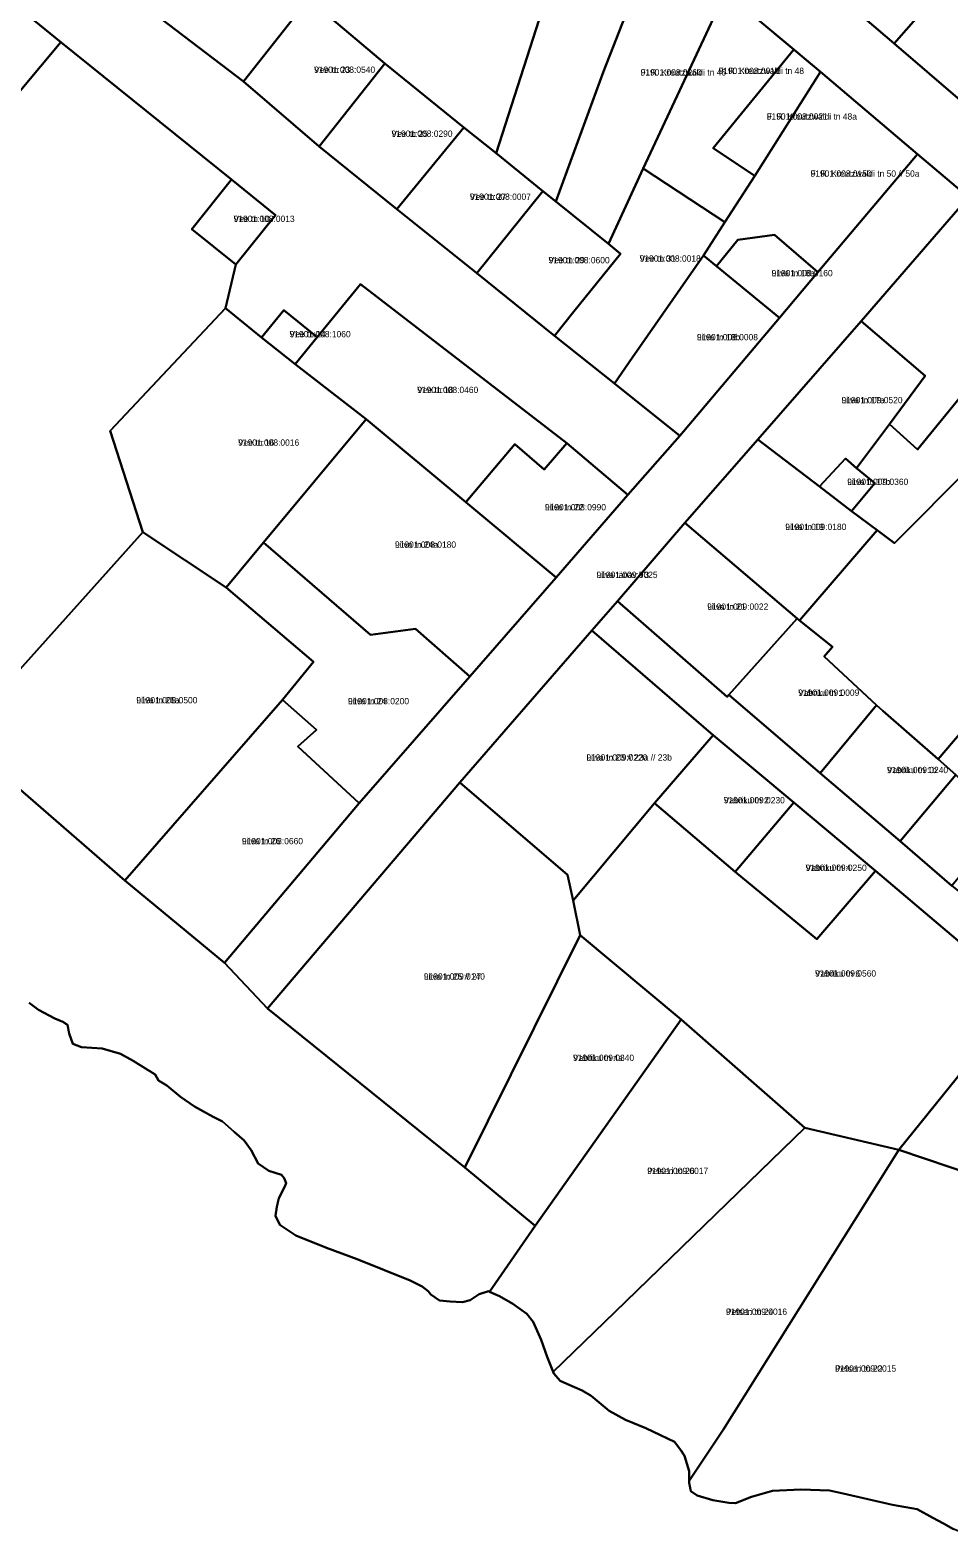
# Model space of a CAD drawing. Extents: x 675810 to 681273, y 6411190 to 6417565.
# Drawn here: x 677826.5 to 678044.7, y 6414897.9 to 6415256.1 of the extents above; entities that cross this region are included whole.
import ezdxf

# ---------------------------------------------------------------- set-up
doc = ezdxf.new("R2010")
doc.units = 0
for name, color, linetype in [('L_AADRESS', 7, 'Continuous'), ('PIIR', 7, 'Continuous'), ('TUNNUS', 7, 'Continuous')]:
    doc.layers.add(name, color=color, linetype=linetype)

msp = doc.modelspace()

# ---------------------------------------------------------------- linework, layer by layer
at = {"layer": 'PIIR'}
for points in [[(678012.96, 6415269), (678038.09, 6415299.36), (678046.57, 6415309.87), (678058.57, 6415324.78), (678069.24, 6415315.72), (678073.05, 6415320.22), (678083.66, 6415311.71), (678061.03, 6415286.5), (678046.56, 6415269.92), (678031.73, 6415252.94)], [(677892.64, 6415263.56), (677934.03, 6415314.81), (677961.35, 6415291.71), (677955.15, 6415284.36), (677947.4, 6415258.61), (677937.16, 6415226.86), (677929.54, 6415233.01), (677910.72, 6415248.23)], [(677975.47, 6415278.9), (677962.72, 6415246.32), (677951.38, 6415215.39), (677948.28, 6415217.88), (677937.16, 6415226.86), (677947.4, 6415258.61), (677955.15, 6415284.36), (677961.35, 6415291.71)], [(677793.94, 6415285.62), (677833.78, 6415253.28), (677776.13, 6415184.33), (677736.95, 6415218.9)], [(677892.64, 6415263.56), (677877.18, 6415243.9), (677857.64, 6415258.81), (677874.22, 6415278.56)], [(677991.64, 6415265.17), (677972.12, 6415223.24), (677963.91, 6415205.32), (677951.38, 6415215.39), (677962.72, 6415246.32), (677975.47, 6415278.9)], [(678046.56, 6415269.92), (678062.66, 6415256.13), (678047.94, 6415239.03), (678031.73, 6415252.94)], [(677910.72, 6415248.23), (677895.15, 6415228.47), (677877.18, 6415243.9), (677892.64, 6415263.56)], [(677991.64, 6415265.17), (678007.94, 6415251.52), (677988.71, 6415228.09), (677998.61, 6415221.54), (677991.52, 6415210.48), (677972.12, 6415223.24)], [(677809.68, 6415088.2), (677743.82, 6415145.67), (677750.89, 6415154.12), (677771.65, 6415178.95), (677776.13, 6415184.33), (677833.78, 6415253.28), (677874.3, 6415220.63), (677864.87, 6415208.84), (677875.38, 6415200.45), (677872.93, 6415190.08), (677845.5, 6415160.96), (677853.28, 6415136.87)], [(678007.94, 6415251.52), (678014.26, 6415246.19), (677998.61, 6415221.54), (677988.71, 6415228.09)], [(677913.61, 6415213.61), (677895.15, 6415228.47), (677910.72, 6415248.23), (677929.54, 6415233.01)], [(678037.29, 6415226.68), (678013.63, 6415198.64), (678003.3, 6415207.5), (677994.63, 6415206.31), (677989.55, 6415200.02), (677986.46, 6415202.56), (677991.52, 6415210.48), (677998.61, 6415221.54), (678014.26, 6415246.19)], [(677929.54, 6415233.01), (677937.16, 6415226.86), (677948.28, 6415217.88), (677932.62, 6415198.39), (677913.61, 6415213.61)], [(678037.29, 6415226.68), (678049.41, 6415216.4), (678023.87, 6415186.98), (677999.36, 6415158.83), (677982.03, 6415139.05), (677965.99, 6415120.49), (677959.89, 6415113.46), (677928.58, 6415077.34), (677882.86, 6415023.65), (677872.66, 6415034.51), (677904.65, 6415072.43), (677930.93, 6415102.56), (677951.46, 6415126.08), (677968.44, 6415145.74), (677980.8, 6415159.74), (678004.47, 6415187.8), (678013.63, 6415198.64)], [(677874.3, 6415220.63), (677884.79, 6415212.15), (677875.38, 6415200.45), (677864.87, 6415208.84)], [(677972.12, 6415223.24), (677991.52, 6415210.48), (677986.46, 6415202.56), (677969.52, 6415178.25), (677965.28, 6415172.19), (677951.06, 6415183.53), (677955.67, 6415189.29), (677966.69, 6415203.01), (677963.91, 6415205.32)], [(677955.67, 6415189.29), (677951.06, 6415183.53), (677932.62, 6415198.39), (677948.28, 6415217.88), (677951.38, 6415215.39), (677963.91, 6415205.32), (677966.69, 6415203.01)], [(678023.87, 6415186.98), (678049.41, 6415216.4), (678070.82, 6415197.78), (678057.06, 6415180.69), (678037.28, 6415156.5), (678030.6, 6415162.51), (678039.09, 6415173.99)], [(678004.47, 6415187.8), (677989.55, 6415200.02), (677994.63, 6415206.31), (678003.3, 6415207.5), (678013.63, 6415198.64)], [(677986.46, 6415202.56), (677989.55, 6415200.02), (678004.47, 6415187.8), (677980.8, 6415159.74), (677965.28, 6415172.19), (677969.52, 6415178.25)], [(677905, 6415195.77), (677954, 6415157.96), (677948.57, 6415151.76), (677941.66, 6415157.79), (677929.96, 6415144.01), (677906.32, 6415163.72), (677889.48, 6415176.74), (677894.7, 6415183.14)], [(677872.93, 6415190.08), (677881.49, 6415183.06), (677889.48, 6415176.74), (677906.32, 6415163.72), (677881.94, 6415134.36), (677873.07, 6415123.73), (677853.28, 6415136.87), (677845.5, 6415160.96)], [(677881.49, 6415183.06), (677886.73, 6415189.56), (677894.7, 6415183.14), (677889.48, 6415176.74)], [(678013.97, 6415147.72), (677999.36, 6415158.83), (678023.87, 6415186.98), (678039.09, 6415173.99), (678030.6, 6415162.51), (678022.82, 6415152.09), (678020.19, 6415154.34)], [(678037.28, 6415156.5), (678057.06, 6415180.69), (678061.01, 6415177.11), (678065.72, 6415172.89), (678068.17, 6415170.73), (678031.79, 6415134.21), (678027.72, 6415137.35), (678021.6, 6415141.8), (678027.17, 6415148.45), (678022.82, 6415152.09), (678030.6, 6415162.51)], [(678069.76, 6415172.45), (678080.05, 6415163.56), (678083.23, 6415148.47), (678075.16, 6415139.39), (678058.19, 6415120.25), (678067.3, 6415112.34), (678042.15, 6415082.88), (678029.02, 6415094.42), (678027.51, 6415095.75), (678015.11, 6415107.3), (678017.12, 6415109.61), (678009.23, 6415115.87), (678027.72, 6415137.35), (678031.79, 6415134.21), (678068.17, 6415170.73)], [(677907.35, 6415112.42), (677881.94, 6415134.36), (677906.32, 6415163.72), (677929.96, 6415144.01), (677951.46, 6415126.08), (677930.93, 6415102.56), (677918.06, 6415113.87)], [(677968.44, 6415145.74), (677951.46, 6415126.08), (677929.96, 6415144.01), (677941.66, 6415157.79), (677948.57, 6415151.76), (677954, 6415157.96)], [(678009.23, 6415115.87), (678008.67, 6415116.35), (677982.03, 6415139.05), (677999.36, 6415158.83), (678013.97, 6415147.72), (678021.6, 6415141.8), (678027.72, 6415137.35)], [(678027.17, 6415148.45), (678021.6, 6415141.8), (678013.97, 6415147.72), (678020.19, 6415154.34), (678022.82, 6415152.09)], [(678131.21, 6415114.51), (678076.01, 6415051.96), (678057.54, 6415067.4), (678046.39, 6415079.16), (678042.15, 6415082.88), (678067.3, 6415112.34), (678072.16, 6415108.18), (678089.26, 6415127.4), (678105.57, 6415145.74), (678123.07, 6415130.89), (678126.3, 6415128.15), (678121.7, 6415122.92)], [(677982.03, 6415139.05), (678008.67, 6415116.35), (677992.48, 6415098.2), (677992.1, 6415097.75), (677965.99, 6415120.49)], [(677886.45, 6415097), (677848.98, 6415054.08), (677809.68, 6415088.2), (677853.28, 6415136.87), (677873.07, 6415123.73), (677893.77, 6415106.07)], [(677873.07, 6415123.73), (677881.94, 6415134.36), (677907.35, 6415112.42), (677918.06, 6415113.87), (677930.93, 6415102.56), (677904.65, 6415072.43), (677890.09, 6415085.9), (677894.49, 6415089.85), (677886.45, 6415097), (677893.77, 6415106.07)], [(677965.99, 6415120.49), (677992.1, 6415097.75), (677992.48, 6415098.2), (678014.15, 6415079.56), (678033.17, 6415063.43), (678045.46, 6415052.81), (678069.54, 6415033.61), (678074.92, 6415029.17), (678099.61, 6415008.07), (678104.32, 6415004.09), (678113.73, 6414996.23), (678133.86, 6414978.84), (678126.85, 6414971.96), (678062.35, 6415026.65), (678027.28, 6415056.39), (678007.87, 6415072.59), (677988.71, 6415088.64), (677959.89, 6415113.46)], [(678009.23, 6415115.87), (678017.12, 6415109.61), (678015.11, 6415107.3), (678027.51, 6415095.75), (678014.15, 6415079.56), (677992.48, 6415098.2), (678008.67, 6415116.35)], [(677928.58, 6415077.34), (677959.89, 6415113.46), (677988.71, 6415088.64), (677974.77, 6415072.44), (677955.51, 6415049.35), (677954.13, 6415055.43)], [(677894.49, 6415089.85), (677890.09, 6415085.9), (677904.65, 6415072.43), (677872.66, 6415034.51), (677848.98, 6415054.08), (677886.45, 6415097)], [(678014.15, 6415079.56), (678027.51, 6415095.75), (678029.02, 6415094.42), (678042.15, 6415082.88), (678046.39, 6415079.16), (678033.17, 6415063.43)], [(677988.71, 6415088.64), (678007.87, 6415072.59), (677994, 6415056.18), (677974.77, 6415072.44)], [(677882.86, 6415023.65), (677928.58, 6415077.34), (677954.13, 6415055.43), (677955.51, 6415049.35), (677957.18, 6415041.12), (677929.79, 6414985.92)], [(678046.39, 6415079.16), (678057.54, 6415067.4), (678045.46, 6415052.81), (678033.17, 6415063.43)], [(677981.13, 6415021.08), (677957.18, 6415041.12), (677955.51, 6415049.35), (677974.77, 6415072.44), (677994, 6415056.18), (678013.38, 6415040.14), (678027.28, 6415056.39), (678062.35, 6415026.65), (678032.85, 6414990.08), (678010.48, 6414995.29)], [(678027.28, 6415056.39), (678013.38, 6415040.14), (677994, 6415056.18), (678007.87, 6415072.59)], [(677929.79, 6414985.92), (677957.18, 6415041.12), (677981.13, 6415021.08), (677946.44, 6414972.03)], [(678032.85, 6414990.08), (678062.35, 6415026.65), (678126.85, 6414971.96), (678113.69, 6414957.3), (678107.35, 6414962.97), (678085.75, 6414972.33), (678051.11, 6414983.88)], [(677981.13, 6415021.08), (678010.48, 6414995.29), (677965.38, 6414951.55), (677950.72, 6414937.38), (677949.33, 6414940.92), (677947.9, 6414944.97), (677946.02, 6414949.2), (677944.45, 6414951.14), (677941.14, 6414953.54), (677938.02, 6414955.31), (677935.65, 6414956.37), (677946.44, 6414972.03)], [(677965.38, 6414951.55), (678010.48, 6414995.29), (678032.85, 6414990.08), (677991.14, 6414923.6), (677983.04, 6414911.49), (677983.06, 6414913.76), (677981.94, 6414917.36), (677981.03, 6414918.76), (677979.57, 6414920.73), (677976.2, 6414922.3), (677972.75, 6414923.99), (677967.89, 6414925.98), (677964.01, 6414928.1), (677959.78, 6414931.64), (677957.61, 6414932.95), (677953.99, 6414934.47), (677952.36, 6414935.18), (677950.87, 6414936.98), (677950.72, 6414937.38)], [(677992.45, 6414906.2), (677988.65, 6414906.85), (677984.94, 6414907.96), (677983.4, 6414909.02), (677983.03, 6414910.96), (677983.04, 6414911.49), (677991.14, 6414923.6), (678032.85, 6414990.08), (678051.11, 6414983.88), (678052.36, 6414910.12), (678052.24, 6414897.91), (678050.05, 6414898.29), (678045.82, 6414899.97), (678043.42, 6414901.31), (678040.91, 6414902.63), (678037.2, 6414904.74), (678031.34, 6414905.74), (678019.61, 6414908.42), (678016.38, 6414909.14), (678009.58, 6414909.37), (678002.82, 6414909.05), (677997.85, 6414907.65), (677994.08, 6414906.17)]]:
    msp.add_lwpolyline(points, close=True, dxfattribs=at)
for points in [[(677806.4, 6415300.64), (677832.58, 6415279.14), (677838.91, 6415273.98), (677857.64, 6415258.81), (677877.18, 6415243.9), (677895.15, 6415228.47), (677913.61, 6415213.61), (677932.62, 6415198.39), (677951.06, 6415183.53), (677965.28, 6415172.19), (677980.8, 6415159.74), (677968.44, 6415145.74), (677954, 6415157.96), (677905, 6415195.77), (677894.7, 6415183.14), (677886.73, 6415189.56), (677881.49, 6415183.06), (677872.93, 6415190.08), (677875.38, 6415200.45), (677884.79, 6415212.15), (677874.3, 6415220.63), (677833.78, 6415253.28), (677793.94, 6415285.62)], [(678012.96, 6415269), (678031.73, 6415252.94), (678047.94, 6415239.03)], [(678049.41, 6415216.4), (678037.29, 6415226.68), (678014.26, 6415246.19), (677991.64, 6415265.17)], [(677809.68, 6415088.2), (677848.98, 6415054.08), (677872.66, 6415034.51), (677882.86, 6415023.65), (677929.79, 6414985.92), (677946.44, 6414972.03), (677935.65, 6414956.37), (677935.4, 6414956.48), (677933.14, 6414955.78), (677931.02, 6414954.36), (677929.19, 6414953.94), (677926.29, 6414954.08), (677923.75, 6414954.29), (677921.64, 6414955.7), (677921.07, 6414956.55), (677919.59, 6414957.61), (677916.77, 6414959.09), (677904.21, 6414964.1), (677896.87, 6414966.85), (677889.6, 6414969.74), (677885.79, 6414972.28), (677884.81, 6414974.4), (677885.09, 6414976.52), (677885.58, 6414978.63), (677886.92, 6414981.24), (677887.28, 6414982.16), (677886.85, 6414983.36), (677886.22, 6414984.14), (677883.18, 6414985.13), (677880.64, 6414986.82), (677879.02, 6414989.99), (677877.33, 6414992.32), (677875, 6414994.37), (677872.18, 6414996.84), (677869.99, 6414997.97), (677867.66, 6414999.17), (677865.55, 6415000.37), (677862.23, 6415002.69), (677858.98, 6415005.37), (677857.01, 6415006.57), (677856.16, 6415007.99), (677851.01, 6415011.23), (677847.98, 6415012.92), (677843.6, 6415014.19), (677838.73, 6415014.48), (677836.62, 6415015.25), (677835.77, 6415017.72), (677835.35, 6415019.77), (677834.29, 6415020.54), (677832.38, 6415021.32), (677828.5, 6415023.37), (677826.24, 6415025.06)], [(677826.24, 6415025.06), (677828.5, 6415023.37), (677832.38, 6415021.32), (677834.29, 6415020.54), (677835.35, 6415019.77), (677835.77, 6415017.72), (677836.62, 6415015.25), (677838.73, 6415014.48), (677843.6, 6415014.19), (677847.98, 6415012.92), (677851.01, 6415011.23), (677856.16, 6415007.99), (677857.01, 6415006.57), (677858.98, 6415005.37), (677862.23, 6415002.69), (677865.55, 6415000.37), (677867.66, 6414999.17), (677869.99, 6414997.97), (677872.18, 6414996.84), (677875, 6414994.37), (677877.33, 6414992.32), (677879.02, 6414989.99), (677880.64, 6414986.82), (677883.18, 6414985.13), (677886.22, 6414984.14), (677886.85, 6414983.36), (677887.28, 6414982.16), (677886.92, 6414981.24), (677885.58, 6414978.63), (677885.09, 6414976.52), (677884.81, 6414974.4), (677885.79, 6414972.28), (677889.6, 6414969.74), (677896.87, 6414966.85), (677904.21, 6414964.1), (677916.77, 6414959.09), (677919.59, 6414957.61), (677921.07, 6414956.55), (677921.64, 6414955.7), (677923.75, 6414954.29), (677926.29, 6414954.08), (677929.19, 6414953.94), (677931.02, 6414954.36), (677933.14, 6414955.78), (677935.4, 6414956.48), (677935.65, 6414956.37), (677938.02, 6414955.31), (677941.14, 6414953.54), (677944.45, 6414951.14), (677946.02, 6414949.2), (677947.9, 6414944.97), (677949.33, 6414940.92), (677950.72, 6414937.38), (677950.87, 6414936.98), (677952.36, 6414935.18), (677953.99, 6414934.47), (677957.61, 6414932.95), (677959.78, 6414931.64), (677964.01, 6414928.1), (677967.89, 6414925.98), (677972.75, 6414923.99), (677976.2, 6414922.3), (677979.57, 6414920.73), (677981.03, 6414918.76), (677981.94, 6414917.36), (677983.06, 6414913.76), (677983.04, 6414911.49), (677983.03, 6414910.96), (677983.4, 6414909.02), (677984.94, 6414907.96), (677988.65, 6414906.85), (677992.45, 6414906.2), (677994.08, 6414906.17), (677997.85, 6414907.65), (678002.82, 6414909.05), (678009.58, 6414909.37), (678016.38, 6414909.14), (678019.61, 6414908.42), (678031.34, 6414905.74), (678037.2, 6414904.74), (678040.91, 6414902.63), (678043.42, 6414901.31), (678045.82, 6414899.97)]]:
    msp.add_lwpolyline(points, dxfattribs=at)

# ---------------------------------------------------------------- texts
at = {"layer": 'L_AADRESS'}
for s, p in [('Vee tn 23', (677893.95, 6415245.97)), ('F. R. Kreutzwaldi tn 46', (677971.51, 6415245.34)), ('F. R. Kreutzwaldi tn 48', (677990.03, 6415245.7)), ('F. R. Kreutzwaldi tn 48a', (678001.48, 6415234.86)), ('Vee tn 25', (677912.34, 6415230.77)), ('F. R. Kreutzwaldi tn 50 // 50a', (678011.88, 6415221.29)), ('Vee tn 27', (677930.95, 6415215.8)), ('Vee tn 10', (677874.83, 6415210.55)), ('Vee tn 29', (677949.65, 6415200.72)), ('Vee tn 31', (677971.29, 6415201.11)), ('Liiva tn 18a', (678002.62, 6415197.65)), ('Vee tn 14', (677888.13, 6415183.15)), ('Liiva tn 18b', (677984.88, 6415182.43)), ('Vee tn 18', (677918.44, 6415169.89)), ('Liiva tn 17a', (678019.23, 6415167.48)), ('Vee tn 16', (677875.91, 6415157.38)), ('Liiva tn 17b', (678020.58, 6415148.07)), ('Liiva tn 22', (677948.79, 6415142.02)), ('Liiva tn 19', (678005.87, 6415137.35)), ('Liiva tn 24a', (677913.17, 6415133.14)), ('Liiva tänav T3', (677961.03, 6415125.97)), ('Liiva tn 21', (677987.33, 6415118.4)), ('Vabriku tn 1', (678008.95, 6415097.96)), ('Liiva tn 26a', (677851.73, 6415096.18)), ('Liiva tn 24', (677902, 6415095.96)), ('Liiva tn 23 // 23a // 23b', (677958.64, 6415082.57)), ('Vabriku tn 1b', (678030.04, 6415079.59)), ('Vabriku tn 2', (677991.26, 6415072.41)), ('Liiva tn 26', (677876.81, 6415062.7)), ('Vabriku tn 4', (678010.71, 6415056.37)), ('Liiva tn 25 // 27', (677920.02, 6415030.53)), ('Vabriku tn 6', (678012.94, 6415031.26)), ('Vabriku tn 4a', (677955.46, 6415011.22)), ('Petseri tn 26', (677973.06, 6414984.34)), ('Petseri tn 24', (677991.79, 6414950.89)), ('Petseri tn 22', (678017.7, 6414937.39))]:
    msp.add_text(s, height=1.5, dxfattribs=at).set_placement(p)
at = {"layer": 'TUNNUS'}
for s, p in [('91901:008:0540', (677893.95, 6415245.97)), ('91901:008:0260', (677971.51, 6415245.34)), ('91901:008:0019', (677990.03, 6415245.7)), ('91901:008:0021', (678001.48, 6415234.86)), ('91901:008:0290', (677912.34, 6415230.77)), ('91901:008:0150', (678011.88, 6415221.29)), ('91901:008:0007', (677930.95, 6415215.8)), ('91901:008:0013', (677874.83, 6415210.55)), ('91901:008:0600', (677949.65, 6415200.72)), ('91901:008:0018', (677971.29, 6415201.11)), ('91901:008:0160', (678002.62, 6415197.65)), ('91901:008:1060', (677888.13, 6415183.15)), ('91901:008:0008', (677984.88, 6415182.43)), ('91901:008:0460', (677918.44, 6415169.89)), ('91901:009:0520', (678019.23, 6415167.48)), ('91901:008:0016', (677875.91, 6415157.38)), ('91901:009:0360', (678020.58, 6415148.07)), ('91901:008:0990', (677948.79, 6415142.02)), ('91901:009:0180', (678005.87, 6415137.35)), ('91901:008:0180', (677913.17, 6415133.14)), ('91901:009:0025', (677961.03, 6415125.97)), ('91901:009:0022', (677987.33, 6415118.4)), ('91901:009:0009', (678008.95, 6415097.96)), ('91901:008:0500', (677851.73, 6415096.18)), ('91901:008:0200', (677902, 6415095.96)), ('91901:009:0220', (677958.64, 6415082.57)), ('91901:009:0240', (678030.04, 6415079.59)), ('91901:009:0230', (677991.26, 6415072.41)), ('91901:008:0660', (677876.81, 6415062.7)), ('91901:009:0250', (678010.71, 6415056.37)), ('91901:009:0140', (677920.02, 6415030.53)), ('91901:009:0560', (678012.94, 6415031.26)), ('91901:009:0340', (677955.46, 6415011.22)), ('91901:009:0017', (677973.06, 6414984.34)), ('91901:009:0016', (677991.79, 6414950.89)), ('91901:009:0015', (678017.7, 6414937.39))]:
    msp.add_text(s, height=1.5, dxfattribs=at).set_placement(p)

doc.saveas('drawing.dxf')
